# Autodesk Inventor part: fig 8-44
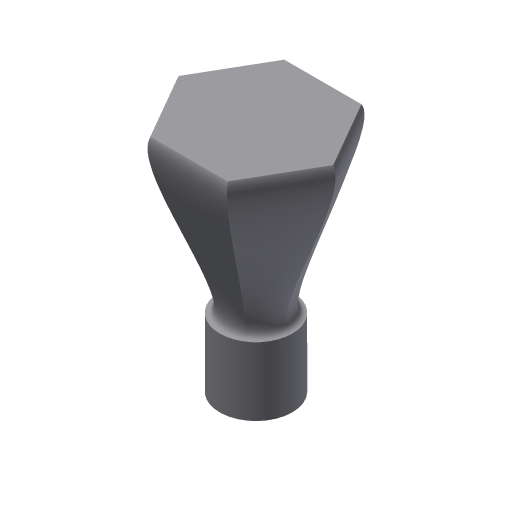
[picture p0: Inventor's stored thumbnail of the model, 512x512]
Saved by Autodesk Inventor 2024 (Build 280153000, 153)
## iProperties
Created: 2004-05
Part Number: fig 8-44
Document SubType Name: Modeling
Designer: CADCIM Technologies
Manufacturer: Standard
Standards Organization: Custom
Density: 1 g/cm^3
Material: Generic
Appearance: Default
Author: CADCIM Technologies
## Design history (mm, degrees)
sketch "Sketch1"
  geometry: C1 r 16.344 at (0, 0)
  constraints: 1 centre point
extrude "Extrusion1" new body sketch "Sketch1" distance "d0" = 30.75; taper "d1" = 0 deg
workplane "Work Plane1"
sketch "Sketch2"
  geometry: L1 (34.788, 0)-(17.394, -30.128); L2 (17.394, -30.128)-(-17.394, -30.128); L3 (-17.394, -30.128)-(-34.788, 0); L4 (-34.788, 0)-(-17.394, 30.128); L5 (-17.394, 30.128)-(17.394, 30.128); L6 (17.394, 30.128)-(34.788, 0); 2 further points
  constraints: 12 end point, 1 coincident, 12 other
loft "Loft2" sketch "Sketch2" dims "d9" = 5, "d10" = 90 deg, "d11" = 40, "d12" = 120 deg
  node "Edges2"
body "Solid1"
other parameters: "d2" = 75
